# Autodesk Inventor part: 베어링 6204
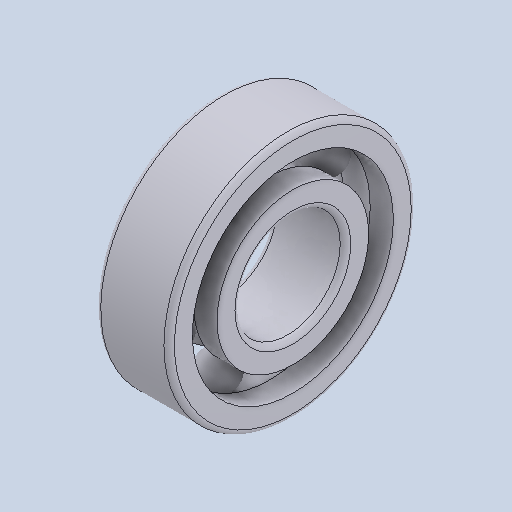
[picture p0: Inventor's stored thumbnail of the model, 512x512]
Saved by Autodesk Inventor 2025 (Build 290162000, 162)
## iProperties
Created: 2024-08
Part Number: 베어링 6204
Material: 강철, 연강
Description: 깊은 그루브 볼 베어링
Document SubType Name: Modeling
Designer: hsj03
Density: 7.86 g/cm^3
Appearance: 기본값
Author: jhkim
Sending System: Autodesk Inventor 2025
Preprocessor: ST-DEVELOPER v20
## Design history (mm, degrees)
feature "Solid1"
feature "Solid1:1"
feature "Solid1:2"
feature "Solid1:3"
feature "Solid1:4"
feature "Solid1:5"
feature "Solid1:6"
feature "Solid1:7"
feature "Solid1:8"
node "솔리드1"
node "솔리드2"
node "솔리드3"
node "솔리드4"
node "솔리드5"
node "솔리드6"
node "솔리드7"
node "솔리드8"
node "솔리드9"
